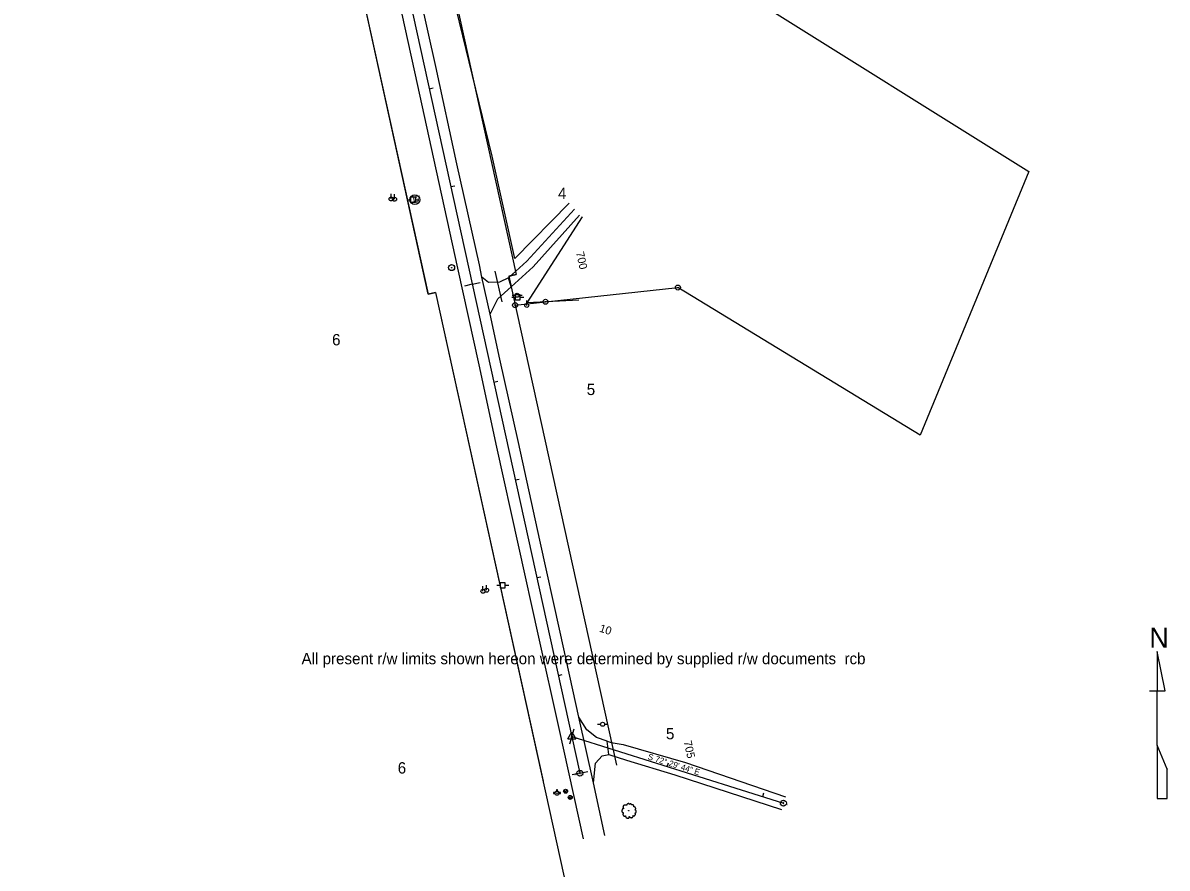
# Model space of a CAD drawing. Extents: x 2519952 to 2531965, y 848341 to 887632.
# Drawn here: x 2522801 to 2523944, y 861093 to 861938 of the extents above; entities that cross this region are included whole.
import ezdxf

# ---------------------------------------------------------------- set-up
doc = ezdxf.new("R2010")
doc.units = 0
for name, color, linetype in [('RD_EX_DR_Pipe', 7, 'Continuous'), ('RD_EX_Driveway', 7, 'Continuous'), ('RD_EX_DV_Prop', 7, 'Continuous'), ('RD_EX_DV_PropPin', 7, 'Continuous'), ('RD_EX_DV_TX_Prop', 7, 'Continuous'), ('RD_EX_Misc', 7, 'Continuous'), ('RD_EX_Road', 7, 'Continuous'), ('RD_EX_RW', 7, 'Continuous'), ('RD_EX_RW_TX', 7, 'Continuous'), ('RD_EX_UT', 7, 'Continuous'), ('RD_EX_VEG', 7, 'Continuous'), ('RD_HC_Cl', 7, 'Continuous'), ('RD_HC_Data', 7, 'Continuous'), ('RD_HC_Data_Tic', 7, 'Continuous'), ('RD_HC_TX_Sta50', 7, 'Continuous'), ('RD_HC_txCode', 7, 'Continuous'), ('RD_SMD_Locator', 7, 'Continuous')]:
    doc.layers.add(name, color=color, linetype=linetype)

msp = doc.modelspace()

# ---------------------------------------------------------------- linework, layer by layer
at = {"layer": 'RD_EX_DR_Pipe'}
msp.add_line((2523279.492560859, 861658.8434420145), (2523272.6163608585, 861689.6409420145), dxfattribs=at)
at = {"layer": 'RD_EX_Driveway'}
for points in [[(2523351.8832608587, 861751.6361420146), (2523304.2182608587, 861699.4835420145), (2523285.9335608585, 861683.0252420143)], [(2523288.436660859, 861673.7647420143), (2523310.2723608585, 861693.8253420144), (2523356.606860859, 861745.6051420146)], [(2523267.3065608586, 861646.6543420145), (2523275.1939608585, 861661.9068420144), (2523288.436660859, 861673.7647420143), (2523285.9335608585, 861683.0252420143), (2523276.6870608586, 861678.5138420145), (2523265.6284608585, 861678.2503420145), (2523259.2835608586, 861683.4840420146)], [(2523370.8057608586, 861178.4698420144), (2523372.7216608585, 861197.9434420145), (2523379.4911608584, 861205.4556420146), (2523386.1150608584, 861206.6785420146), (2523384.5154608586, 861220.1266420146), (2523373.8118608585, 861223.7307420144), (2523364.121960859, 861231.4083420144), (2523356.1880608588, 861244.1937420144)]]:
    msp.add_lwpolyline(points, dxfattribs=at)
at = {"layer": 'RD_EX_DV_Prop'}
for p, q in [((2523132.252656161, 862418.5270053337), (2523293.5404425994, 861686.0747884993)), ((2523205.646176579, 861666.7202541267), (2523044.3583901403, 862399.1724709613)), ((2523185.3646079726, 862177.331018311), (2523805.6610062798, 861789.067429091)), ((2523805.6610062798, 861789.067429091), (2523697.298254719, 861525.8613431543)), ((2523286.215920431, 861684.4619106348), (2523293.5404425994, 861686.0747884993)), ((2523286.215918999, 861684.4619103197), (2523393.7411116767, 861196.160431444)), ((2523322.6906608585, 861658.9656420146), (2523455.104160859, 861673.2117420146)), ((2523697.298254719, 861525.8613431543), (2523455.104160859, 861673.2117420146)), ((2523212.9706987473, 861668.3331319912), (2523205.646176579, 861666.7202541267)), ((2523212.970697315, 861668.3331316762), (2523409.5649383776, 860775.5446022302)), ((2523292.3469608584, 861655.6116420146), (2523292.5635477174, 861655.6355821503)), ((2523292.5635477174, 861655.6355821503), (2523322.6906608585, 861658.9656420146))]:
    msp.add_line(p, q, dxfattribs=at)
at = {"layer": 'RD_EX_DV_PropPin'}
for centre, radius in [((2523455.104140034, 861673.2117316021), 2.499000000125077), ((2523455.104140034, 861673.2117420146), 0.24990000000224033), ((2523322.690640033, 861658.9656316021), 2.499000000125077), ((2523292.346940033, 861655.611631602), 2.499000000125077), ((2523292.346940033, 861655.6116420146), 0.24990000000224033), ((2523322.690640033, 861658.9656420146), 0.24990000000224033)]:
    msp.add_circle(centre, radius, dxfattribs=at)
at = {"layer": 'RD_EX_Misc'}
for p, q in [((2523941.943013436, 861270.466222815), (2523934.103013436, 861309.6678894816)), ((2523934.103013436, 861309.6678894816), (2523934.103013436, 861309.6678894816)), ((2523934.103013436, 861309.6678894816), (2523934.103013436, 861270.466222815)), ((2523926.263013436, 861270.466222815), (2523934.103013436, 861270.466222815)), ((2523934.103013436, 861216.070722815), (2523934.103013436, 861270.466222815)), ((2523934.103013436, 861270.466222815), (2523941.943013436, 861270.466222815)), ((2523941.943013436, 861270.466222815), (2523941.943013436, 861270.931222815)), ((2523943.903013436, 861192.0645561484), (2523934.103013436, 861216.070722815)), ((2523934.103013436, 861216.070722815), (2523934.103013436, 861162.6628894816)), ((2523943.903013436, 861162.6628894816), (2523943.903013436, 861192.336222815)), ((2523943.903013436, 861192.336222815), (2523943.903013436, 861192.0645561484)), ((2523934.103013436, 861162.6628894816), (2523943.903013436, 861162.6628894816))]:
    msp.add_line(p, q, dxfattribs=at)
at = {"layer": 'RD_EX_Road'}
for p, q in [((2523213.0670608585, 861894.0415420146), (2523190.4317608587, 861997.6372420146)), ((2523192.1267608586, 861888.7699420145), (2523169.589360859, 861991.4271420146)), ((2523234.1250608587, 861796.7883420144), (2523213.0670608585, 861894.0415420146)), ((2523213.7762608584, 861789.8921420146), (2523192.1267608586, 861888.7699420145)), ((2523235.262860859, 861692.3933420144), (2523213.7762608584, 861789.8921420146)), ((2523256.6700608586, 861695.9737420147), (2523234.1250608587, 861796.7883420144)), ((2523259.2835608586, 861683.4840420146), (2523256.6700608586, 861695.9737420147)), ((2523256.4608608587, 861595.9754420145), (2523235.262860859, 861692.3933420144)), ((2523267.3065608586, 861646.6543420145), (2523259.2835608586, 861683.4840420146)), ((2523277.1733608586, 861601.7131420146), (2523267.3065608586, 861646.6543420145)), ((2523274.2687608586, 861513.8392420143), (2523256.4608608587, 861595.9754420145)), ((2523295.6146608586, 861518.3557420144), (2523277.1733608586, 861601.7131420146)), ((2523295.8794608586, 861415.7624420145), (2523274.2687608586, 861513.8392420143)), ((2523316.9803608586, 861420.9021420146), (2523295.6146608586, 861518.3557420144)), ((2523316.1848608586, 861323.9049420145), (2523295.8794608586, 861415.7624420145)), ((2523337.5580608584, 861328.7830420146), (2523316.9803608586, 861420.9021420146)), ((2523336.3015608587, 861232.8469420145), (2523316.1848608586, 861323.9049420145)), ((2523356.1880608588, 861244.1937420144), (2523337.5580608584, 861328.7830420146)), ((2523370.8057608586, 861178.4698420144), (2523356.1880608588, 861244.1937420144)), ((2523360.577560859, 861122.5731420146), (2523336.3015608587, 861232.8469420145)), ((2523381.9277608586, 861125.7231420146), (2523370.8057608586, 861178.4698420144))]:
    msp.add_line(p, q, dxfattribs=at)
for points in [[(2523384.5154608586, 861220.1266420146), (2523388.4468608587, 861218.8818420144), (2523400.5237608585, 861216.6896420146), (2523462.7807608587, 861198.6467420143), (2523562.4737608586, 861164.4697420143)], [(2523386.1150608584, 861206.6785420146), (2523403.5274608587, 861201.0439420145), (2523451.9305608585, 861186.3875420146), (2523558.610160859, 861151.9120420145)]]:
    msp.add_lwpolyline(points, dxfattribs=at)
at = {"layer": 'RD_EX_RW'}
for p, q in [((2523286.2158867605, 861684.4619032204), (2523393.7410717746, 861196.1604310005)), ((2523212.9706650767, 861668.3331245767), (2523320.495849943, 861180.0316530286))]:
    msp.add_line(p, q, dxfattribs=at)
for points in [[(2523124.9281339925, 862416.9141274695), (2523132.252656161, 862418.5270053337), (2523293.5404425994, 861686.0747884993), (2523286.215920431, 861684.4619106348)], [(2523051.6828853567, 862400.7853428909), (2523044.3583901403, 862399.1724709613), (2523205.646176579, 861666.7202541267), (2523212.9706650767, 861668.3331245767)]]:
    msp.add_lwpolyline(points, dxfattribs=at)
at = {"layer": 'RD_EX_UT'}
for p, q in [((2523168.5386608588, 861761.6613420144), (2523168.5386608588, 861766.6613420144)), ((2523171.9362608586, 861761.4070420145), (2523171.9362608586, 861766.4070420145)), ((2523184.284094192, 861760.9212086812), (2523187.753260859, 861760.9212086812)), ((2523192.7151775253, 861763.4836253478), (2523187.7151775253, 861763.4836253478)), ((2523187.7151775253, 861763.4836253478), (2523187.7151775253, 861758.4836253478)), ((2523187.7151775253, 861758.4836253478), (2523192.7151775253, 861758.4836253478)), ((2523190.0479108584, 861758.7058753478), (2523194.6770775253, 861758.7058753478)), ((2523192.6436775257, 861760.9212086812), (2523196.284094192, 861760.9212086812)), ((2523192.7151775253, 861758.4836253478), (2523192.7151775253, 861763.4836253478)), ((2523288.981594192, 861663.4201086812), (2523292.4507608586, 861663.4201086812)), ((2523289.4071775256, 861665.4845920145), (2523292.3377608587, 861665.4845920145)), ((2523297.412677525, 861665.9825253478), (2523292.412677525, 861665.9825253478)), ((2523292.412677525, 861665.9825253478), (2523292.412677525, 861660.9825253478)), ((2523296.3376775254, 861665.4845920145), (2523299.4071775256, 861665.4845920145)), ((2523297.341177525, 861663.4201086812), (2523300.981594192, 861663.4201086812)), ((2523297.412677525, 861660.9825253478), (2523297.412677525, 861665.9825253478)), ((2523292.412677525, 861660.9825253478), (2523297.412677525, 861660.9825253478)), ((2523304.0557608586, 861655.2612420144), (2523304.0557608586, 861660.2612420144)), ((2523263.9140608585, 861370.8840420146), (2523263.9140608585, 861375.8840420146)), ((2523274.081594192, 861375.808008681), (2523277.5507608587, 861375.808008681)), ((2523282.512677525, 861378.3704253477), (2523277.512677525, 861378.3704253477)), ((2523277.512677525, 861378.3704253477), (2523277.512677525, 861373.3704253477)), ((2523282.441177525, 861375.808008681), (2523286.081594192, 861375.808008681)), ((2523282.512677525, 861373.3704253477), (2523282.512677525, 861378.3704253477)), ((2523260.2944608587, 861369.8212420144), (2523260.2944608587, 861374.8212420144)), ((2523277.512677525, 861373.3704253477), (2523282.512677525, 861373.3704253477)), ((2523374.8744775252, 861236.9509920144), (2523377.805060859, 861236.9509920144)), ((2523381.8049775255, 861236.9509920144), (2523384.8744775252, 861236.9509920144)), ((2523333.735294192, 861171.3450586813), (2523333.735294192, 861170.0712253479)), ((2523334.735460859, 861171.3450586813), (2523333.735294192, 861171.3450586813)), ((2523334.735460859, 861170.0489753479), (2523334.735460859, 861171.3450586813)), ((2523342.8986608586, 861168.0732920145), (2523341.594994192, 861171.5558753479)), ((2523342.8986608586, 861168.0732920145), (2523344.220910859, 861171.5186253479)), ((2523332.276377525, 861168.6975586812), (2523330.718960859, 861168.6975586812)), ((2523330.718960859, 861168.6975586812), (2523330.718960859, 861167.6975586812)), ((2523330.718960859, 861167.6975586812), (2523332.238460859, 861167.6975586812)), ((2523337.718960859, 861168.6975586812), (2523336.1084608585, 861168.6975586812)), ((2523336.1463775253, 861167.6975586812), (2523337.718960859, 861167.6975586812)), ((2523337.718960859, 861167.6975586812), (2523337.718960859, 861168.6975586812)), ((2523347.4475608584, 861161.8692920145), (2523346.143894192, 861165.3518753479)), ((2523347.4475608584, 861161.8692920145), (2523348.7698108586, 861165.3146253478))]:
    msp.add_line(p, q, dxfattribs=at)
for centre, radius in [((2523192.1761441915, 861760.9140086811), 4.908479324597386), ((2523168.538672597, 861761.661355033), 1.9992000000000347), ((2523171.936272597, 861761.4070550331), 1.9992000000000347), ((2523294.3377608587, 861665.4693420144), 2.000000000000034), ((2523304.055772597, 861655.261255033), 1.9992000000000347), ((2523260.294472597, 861369.821255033), 1.9992000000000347), ((2523263.9140725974, 861370.8840550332), 1.9992000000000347), ((2523379.805060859, 861236.9357420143), 2.000000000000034), ((2523334.1924296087, 861168.124162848), 2.0000000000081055), ((2523342.8986816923, 861170.0660003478), 2.0000000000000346), ((2523334.1924608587, 861168.1241420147), 0.2500000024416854), ((2523347.4475816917, 861163.8620003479), 2.0000000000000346)]:
    msp.add_circle(centre, radius, dxfattribs=at)
for start, end in [(74.24552500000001, 103.21276111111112), (163.33869722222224, 192.31501666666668), (347.6849833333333, 16.661302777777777)]:
    msp.add_arc((2523334.1924296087, 861168.124162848), 2.0000000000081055, start, end, dxfattribs=at)
at = {"layer": 'RD_EX_VEG'}
for points in [[(2523346.2863608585, 861757.6143420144), (2523292.1346608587, 861702.2212420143), (2523269.3937608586, 861804.2864420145), (2523220.430360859, 862005.5490420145), (2523230.2419608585, 862027.7940420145), (2523277.332460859, 861999.0390420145)], [(2523356.0478608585, 861660.6643420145), (2523304.2731608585, 861657.8064420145), (2523359.6938608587, 861743.8552420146)]]:
    msp.add_lwpolyline(points, dxfattribs=at)
for centre, radius in [((2523405.9625816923, 861150.5627628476), 0.2500000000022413), ((2523405.950029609, 861150.543908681), 0.00010000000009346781)]:
    msp.add_circle(centre, radius, dxfattribs=at)
for points in [[(2523406.0944775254, 861157.7299920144), (2523405.794644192, 861157.7549920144), (2523405.469810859, 861157.6549920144), (2523405.219894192, 861157.5550753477), (2523404.9949775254, 861157.4800753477), (2523404.7700608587, 861157.3800753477), (2523404.4702275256, 861157.2052420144), (2523404.245310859, 861157.0052420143), (2523404.120310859, 861156.755408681), (2523404.0703108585, 861156.5304920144), (2523404.020394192, 861156.255658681), (2523404.020394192, 861156.080658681), (2523403.8954775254, 861156.0556586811), (2523403.7454775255, 861156.080658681), (2523403.495644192, 861156.1556586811), (2523403.2457275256, 861156.1556586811), (2523402.995810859, 861156.1556586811), (2523402.6459775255, 861156.130658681), (2523402.296144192, 861156.130658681), (2523402.021310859, 861156.080658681), (2523401.696394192, 861156.0307420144), (2523401.3215608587, 861155.9058253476), (2523400.9717275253, 861155.7808253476), (2523400.671894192, 861155.530908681), (2523400.4219775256, 861155.056158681), (2523400.2969775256, 861154.7063253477), (2523400.1470608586, 861154.456408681), (2523400.2969775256, 861154.006658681), (2523400.4719775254, 861153.6567420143), (2523400.496894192, 861153.4568253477), (2523400.571894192, 861153.0320753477), (2523400.671894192, 861152.807158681), (2523400.796810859, 861152.607158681), (2523400.721894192, 861152.5822420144), (2523400.3469775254, 861152.5322420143), (2523400.0471441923, 861152.4323253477), (2523399.6223108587, 861152.207408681), (2523399.397394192, 861151.9824920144), (2523399.297394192, 861151.6575753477), (2523399.2724775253, 861151.3077420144), (2523399.1725608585, 861151.107908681), (2523399.097560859, 861150.8329920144), (2523399.072560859, 861150.7579920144), (2523399.0225608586, 861150.433158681), (2523399.1225608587, 861149.9833253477), (2523399.1475608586, 861149.6334920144), (2523399.2724775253, 861149.4085753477), (2523399.422394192, 861149.2337420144), (2523399.597310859, 861148.9838253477), (2523399.997144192, 861148.758908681), (2523400.3219775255, 861148.658908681), (2523400.521894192, 861148.6339920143), (2523400.3469775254, 861148.134158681), (2523400.2969775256, 861147.7843253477), (2523400.172060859, 861147.3844920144), (2523400.172060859, 861147.3095753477), (2523400.122144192, 861146.8347420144), (2523400.271977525, 861146.5098253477), (2523400.3469775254, 861146.1350753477), (2523400.521894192, 861145.910158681), (2523400.796810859, 861145.6102420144), (2523401.121644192, 861145.385408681), (2523401.621477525, 861145.260408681), (2523402.021310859, 861145.285408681), (2523402.5960608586, 861145.4603253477), (2523402.845894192, 861145.5353253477), (2523402.820894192, 861145.360408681), (2523402.845894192, 861144.9854920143), (2523402.845894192, 861144.5607420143), (2523402.995810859, 861144.2359086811), (2523403.0958108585, 861143.9609920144), (2523403.2457275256, 861143.7110753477), (2523403.570644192, 861143.4862420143), (2523403.9703941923, 861143.4112420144), (2523404.3952275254, 861143.2613253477), (2523404.845060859, 861143.1863253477), (2523405.344810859, 861143.1613253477), (2523405.944560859, 861143.3112420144), (2523406.219394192, 861143.4362420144), (2523406.319394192, 861143.611158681), (2523406.5193108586, 861143.9859920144), (2523406.4693108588, 861144.210908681), (2523406.4943108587, 861144.810658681), (2523406.5942275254, 861144.635658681), (2523406.769227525, 861144.2858253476), (2523407.268977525, 861143.9859920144), (2523407.668810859, 861143.8110753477), (2523408.143560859, 861143.6610753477), (2523408.4434775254, 861143.5861586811), (2523408.9182275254, 861143.6610753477), (2523409.293144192, 861143.7360753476), (2523409.667894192, 861143.8610753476), (2523409.9678108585, 861144.1359086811), (2523410.1427275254, 861144.4108253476), (2523410.1927275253, 861144.685658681), (2523410.267644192, 861145.0604920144), (2523410.317644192, 861145.235408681)], [(2523410.317644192, 861145.235408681), (2523410.2427275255, 861145.410408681), (2523410.1927275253, 861145.6602420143), (2523410.267644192, 861145.6352420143), (2523410.4425608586, 861145.5852420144), (2523410.7174775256, 861145.4603253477), (2523410.942394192, 861145.385408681), (2523411.2672275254, 861145.410408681), (2523411.542144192, 861145.5103253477), (2523411.991894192, 861145.7852420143), (2523412.2668108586, 861146.2599920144), (2523412.5416441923, 861146.6598253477), (2523412.616644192, 861146.984658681), (2523412.566644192, 861147.2095753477), (2523412.5416441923, 861147.7093253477), (2523412.3417275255, 861147.9592420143), (2523412.291727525, 861148.084158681), (2523412.191810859, 861148.4839920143), (2523412.2668108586, 861148.5339920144), (2523412.5416441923, 861148.5839920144), (2523412.9164775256, 861148.7089086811), (2523413.191394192, 861148.8338253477), (2523413.416310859, 861149.0088253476), (2523413.4912275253, 861149.2337420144), (2523413.4663108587, 861149.6334920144), (2523413.516227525, 861150.0333253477), (2523413.441310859, 861150.1833253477), (2523413.3413108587, 861150.333158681), (2523413.2663108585, 861150.533158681), (2523413.116394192, 861150.6829920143), (2523413.0164775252, 861150.8329920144), (2523412.9164775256, 861150.932908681), (2523412.791560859, 861151.082908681), (2523412.616644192, 861151.2078253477), (2523412.4667275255, 861151.2578253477), (2523412.416727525, 861151.4077420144), (2523412.566644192, 861151.607658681), (2523412.616644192, 861151.7075753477), (2523412.6415608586, 861151.9324920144), (2523412.8665608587, 861152.2823253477), (2523412.9164775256, 861152.682158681), (2523412.8665608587, 861153.1069920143), (2523412.816560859, 861153.381908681), (2523412.666560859, 861153.6567420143), (2523412.4667275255, 861153.906658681), (2523412.3417275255, 861154.0815753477), (2523412.1668108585, 861154.2064920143), (2523411.8419775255, 861154.3314920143), (2523411.592060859, 861154.381408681), (2523411.2422275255, 861154.381408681), (2523411.0423108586, 861154.431408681), (2523411.0673108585, 861154.481408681), (2523411.0673108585, 861154.6313253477), (2523411.0673108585, 861154.9062420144), (2523410.992310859, 861155.3559920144), (2523410.8423941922, 861155.8558253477), (2523410.8423941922, 861155.8808253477), (2523410.742394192, 861156.130658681), (2523410.5175608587, 861156.3305753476), (2523410.3426441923, 861156.4304920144), (2523410.1427275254, 861156.5554920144), (2523409.892810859, 861156.5804920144), (2523409.592977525, 861156.5804920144), (2523409.3180608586, 861156.5304920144), (2523409.1181441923, 861156.4304920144), (2523408.9432275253, 861156.3055753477), (2523408.8682275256, 861156.4554920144), (2523408.768310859, 861156.755408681), (2523408.7183108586, 861156.9053253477), (2523408.568394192, 861157.0802420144), (2523408.3435608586, 861157.280158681), (2523407.8936441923, 861157.4050753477), (2523407.268977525, 861157.330158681), (2523406.9690608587, 861157.1302420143), (2523406.819144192, 861156.9553253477), (2523406.769227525, 861157.0802420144), (2523406.5692275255, 861157.280158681), (2523406.4693108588, 861157.4550753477), (2523406.2943941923, 861157.5800753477), (2523406.1444775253, 861157.6799920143), (2523406.0444775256, 861157.7299920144)]]:
    msp.add_spline(points, degree=3, dxfattribs=at)
at = {"layer": 'RD_HC_Cl'}
for p, q in [((2522800.5248940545, 863715.7406869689), (2523357.1184608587, 861188.0960420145)), ((2523349.0291608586, 861224.8317420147), (2523560.5230608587, 861158.1294420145))]:
    msp.add_line(p, q, dxfattribs=at)
at = {"layer": 'RD_HC_Data'}
for p, q in [((2523345.058420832, 861222.5390104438), (2523349.030391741, 861229.4186658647)), ((2523349.030391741, 861229.4186658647), (2523352.9990874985, 861222.5390104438)), ((2523345.058420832, 861222.5390104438), (2523352.9990874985, 861222.5390104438))]:
    msp.add_line(p, q, dxfattribs=at)
for centre, radius in [((2523228.972619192, 861693.0909524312), 3.000000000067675), ((2523228.9726608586, 861693.0909420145), 0.28181953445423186), ((2523349.0291608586, 861224.8317420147), 0.5294348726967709), ((2523357.118419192, 861188.0960524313), 3.000000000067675), ((2523357.1184608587, 861188.0960420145), 0.28181953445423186), ((2523560.5230191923, 861158.1294524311), 3.000000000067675), ((2523560.5230608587, 861158.1294420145), 0.28181953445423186)]:
    msp.add_circle(centre, radius, dxfattribs=at)
at = {"layer": 'RD_HC_Data_Tic'}
for p, q in [((2523206.5837319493, 861871.7156957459), (2523210.49014378, 861872.5758972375)), ((2523228.088769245, 861774.0553999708), (2523231.9951810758, 861774.9156014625)), ((2523249.593806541, 861676.3951041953), (2523241.780982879, 861674.6747012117)), ((2523249.593806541, 861676.3951041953), (2523257.406630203, 861678.115507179)), ((2523271.098843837, 861578.7348084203), (2523275.005255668, 861579.5950099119)), ((2523292.6038811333, 861481.0745126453), (2523296.510292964, 861481.9347141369)), ((2523314.108918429, 861383.4142168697), (2523318.0153302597, 861384.2744183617)), ((2523335.613955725, 861285.7539210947), (2523339.520367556, 861286.6141225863)), ((2523349.0291608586, 861224.8317420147), (2523351.435415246, 861232.4612858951)), ((2523349.0291608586, 861224.8317420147), (2523346.622906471, 861217.2021981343)), ((2523444.3984593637, 861194.7535621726), (2523445.6015865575, 861198.5683341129)), ((2523357.1189930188, 861188.093625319), (2523349.3061693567, 861186.3732223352)), ((2523357.1189930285, 861188.0936253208), (2523364.9318166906, 861189.8140283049)), ((2523539.7677578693, 861164.6753823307), (2523540.970885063, 861168.4901542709))]:
    msp.add_line(p, q, dxfattribs=at)
at = {"layer": 'RD_SMD_Locator'}
for centre in [(2523213.0670608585, 861894.0415420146), (2523192.1267608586, 861888.7699420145), (2523269.3937608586, 861804.2864420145), (2523213.7762608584, 861789.8921420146), (2523234.1250608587, 861796.7883420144), (2523346.2863608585, 861757.6143420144), (2523351.8832608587, 861751.6361420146), (2523356.606860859, 861745.6051420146), (2523359.6938608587, 861743.8552420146), (2523256.6700608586, 861695.9737420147), (2523292.1346608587, 861702.2212420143), (2523304.2182608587, 861699.4835420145), (2523228.9726608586, 861693.0909420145), (2523235.262860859, 861692.3933420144), (2523272.6163608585, 861689.6409420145), (2523310.2723608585, 861693.8253420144), (2523259.2835608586, 861683.4840420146), (2523259.2835608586, 861683.4840420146), (2523265.6284608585, 861678.2503420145), (2523276.6870608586, 861678.5138420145), (2523285.9335608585, 861683.0252420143), (2523285.9335608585, 861683.0252420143), (2523288.436660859, 861673.7647420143), (2523288.436660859, 861673.7647420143), (2523275.1939608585, 861661.9068420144), (2523279.492560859, 861658.8434420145), (2523304.2731608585, 861657.8064420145), (2523356.0478608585, 861660.6643420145), (2523267.3065608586, 861646.6543420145), (2523267.3065608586, 861646.6543420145), (2523256.4608608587, 861595.9754420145), (2523277.1733608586, 861601.7131420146), (2523274.2687608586, 861513.8392420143), (2523295.6146608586, 861518.3557420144), (2523295.8794608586, 861415.7624420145), (2523316.9803608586, 861420.9021420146), (2523316.1848608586, 861323.9049420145), (2523337.5580608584, 861328.7830420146), (2523356.1880608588, 861244.1937420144), (2523356.1880608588, 861244.1937420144), (2523336.3015608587, 861232.8469420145), (2523364.121960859, 861231.4083420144), (2523349.0291608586, 861224.8317420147), (2523373.8118608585, 861223.7307420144), (2523384.5154608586, 861220.1266420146), (2523384.5154608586, 861220.1266420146), (2523388.4468608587, 861218.8818420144), (2523400.5237608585, 861216.6896420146), (2523379.4911608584, 861205.4556420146), (2523386.1150608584, 861206.6785420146), (2523386.1150608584, 861206.6785420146), (2523372.7216608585, 861197.9434420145), (2523403.5274608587, 861201.0439420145), (2523462.7807608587, 861198.6467420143), (2523357.1184608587, 861188.0960420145), (2523451.9305608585, 861186.3875420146), (2523370.8057608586, 861178.4698420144), (2523370.8057608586, 861178.4698420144), (2523560.5230608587, 861158.1294420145), (2523562.4737608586, 861164.4697420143), (2523558.610160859, 861151.9120420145), (2523381.9277608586, 861125.7231420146), (2523360.577560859, 861122.5731420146)]:
    msp.add_circle(centre, 0.001, dxfattribs=at)

# ---------------------------------------------------------------- texts
at = {"layer": 'RD_EX_DV_TX_Prop'}
for s, p in [('4', (2523335.218822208, 861761.5873291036)), ('6', (2523109.501591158, 861615.4343723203)), ('5', (2523363.99007099, 861565.8019896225)), ('5', (2523443.1167169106, 861221.9396494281)), ('6', (2523175.0840513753, 861187.7226752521))]:
    msp.add_text(s, height=11.31666660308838, dxfattribs=at).set_placement(p)
at = {"layer": 'RD_EX_Misc'}
msp.add_text('N', height=19.999999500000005, dxfattribs=at).set_placement((2523926.210263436, 861313.3740561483))
at = {"layer": 'RD_EX_RW_TX'}
msp.add_text('All present r/w limits shown hereon were determined by supplied r/w documents  rcb', height=11.31666660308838, dxfattribs=at).set_placement((2523078.9895708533, 861296.9305425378))
at = {"layer": 'RD_EX_UT'}
msp.add_text('W', height=6.000000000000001, dxfattribs=at).set_placement((2523189.7114108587, 861758.9130420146))
at = {"layer": 'RD_HC_Data'}
msp.add_text('S 72%%d 29\' 44" E', height=6, rotation=342.4954342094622, dxfattribs=at).set_placement((2523424.439591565, 861202.0968731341))
at = {"layer": 'RD_HC_TX_Sta50'}
for s, height, rotation, p in [('700', 7.999999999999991, 282.41848259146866, (2523353.188700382, 861708.1500840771)), ('10', 8.000000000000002, 342.4954342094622, (2523375.9865530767, 861329.5737382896)), ('705', 7.99999999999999, 282.41848259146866, (2523460.7566239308, 861219.6545244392))]:
    msp.add_text(s, height=height, rotation=rotation, dxfattribs=at).set_placement(p)
at = {"layer": 'RD_HC_txCode'}
for s, p in [('CP 1 PSC', (2523225.9726608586, 861691.0909420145)), ('1', (2523228.9726608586, 861694.0909420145)), ('27', (2523348.2968773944, 861225.8317420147)), ('PI 10+00.00', (2523345.0527829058, 861222.8317420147)), ('POT 705+00.00', (2523351.2759411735, 861186.0960420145)), ('15', (2523356.669641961, 861189.0960420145)), ('28', (2523559.790777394, 861159.1294420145)), ('POT 12+21.76', (2523555.8695175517, 861156.1294420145))]:
    msp.add_text(s, height=1.0000000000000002, dxfattribs=at).set_placement(p)

doc.saveas('drawing.dxf')
